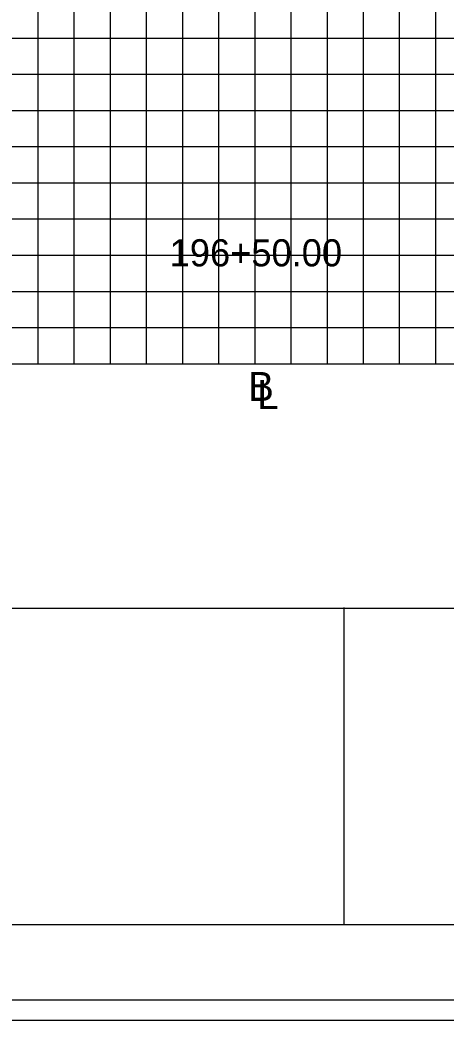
# Model space of a CAD drawing. Extents: x 967 to 1326, y 964 to 2304.
# Drawn here: x 1147 to 1170.6, y 1243.7 to 1299 of the extents above; entities that cross this region are included whole.
import ezdxf

# ---------------------------------------------------------------- set-up
doc = ezdxf.new("R2010")
doc.units = 0
for name, color, linetype in [('Default', 7, 'Continuous'), ('RD_GPK_XS_Cell', 7, 'Continuous'), ('RD_PD_PaveShd', 7, 'Continuous'), ('RD_XS_ExGround', 7, 'Continuous'), ('RD_XS_ExPaveRet', 7, 'Continuous'), ('RD_XS_PaveOvlay', 7, 'Continuous'), ('RD_XS_TX_Elev_EX', 7, 'Continuous')]:
    doc.layers.add(name, color=color, linetype=linetype)

msp = doc.modelspace()

# ---------------------------------------------------------------- linework, layer by layer
at = {"layer": 'RD_GPK_XS_Cell'}
for p, q in [((1150, 1280), (1150, 1450)), ((1160, 1280), (1160, 1450)), ((1170, 1280), (1170, 1450)), ((1000, 1290), (1320, 1290)), ((1000, 1280), (1320, 1280))]:
    msp.add_line(p, q, dxfattribs=at)
at = {"layer": 'RD_PD_PaveShd'}
for p, q in [((996.114, 1266.486), (1323.886, 1266.486)), ((1164.932, 1248.983), (1164.932, 1266.526)), ((1323.886, 1248.983), (996.114, 1248.983))]:
    msp.add_line(p, q, dxfattribs=at)
at = {"layer": 'RD_XS_ExGround'}
for p, q in [((1148, 1280), (1148, 1450)), ((1152, 1280), (1152, 1450)), ((1154, 1280), (1154, 1450)), ((1156, 1280), (1156, 1450)), ((1158, 1280), (1158, 1450)), ((1162, 1280), (1162, 1450)), ((1164, 1280), (1164, 1450)), ((1166, 1280), (1166, 1450)), ((1168, 1280), (1168, 1450)), ((1000, 1298), (1320, 1298)), ((1000, 1296), (1320, 1296)), ((1000, 1294), (1320, 1294)), ((1000, 1292), (1320, 1292)), ((1000, 1288), (1320, 1288)), ((1000, 1286), (1320, 1286)), ((1000, 1284), (1320, 1284)), ((1000, 1282), (1320, 1282))]:
    msp.add_line(p, q, dxfattribs=at)
at = {"layer": 'RD_XS_PaveOvlay'}
msp.add_lwpolyline([(967.409, 1243.72), (1326.285, 1243.72), (1326.285, 1463.72), (967.409, 1463.72)], close=True, dxfattribs=at)
at = {"layer": 'RD_XS_TX_Elev_EX'}
for points in [[(967.409, 1243.72), (1326.285, 1243.72), (1326.285, 1463.72), (967.409, 1463.72)], [(988.525, 1244.84), (1326.285, 1244.84), (1326.285, 1462.6), (988.525, 1462.6)]]:
    msp.add_lwpolyline(points, close=True, dxfattribs=at)

# ---------------------------------------------------------------- texts
at = {"layer": 'Default'}
msp.add_text('196+50.00', height=1.5, dxfattribs=at).set_placement((1155.278, 1285.381))
at = {"layer": 'RD_XS_ExPaveRet'}
for s, p in [('B', (1159.615, 1277.941)), ('L', (1160.124, 1277.491))]:
    msp.add_text(s, height=1.6, dxfattribs=at).set_placement(p)

doc.saveas('drawing.dxf')
